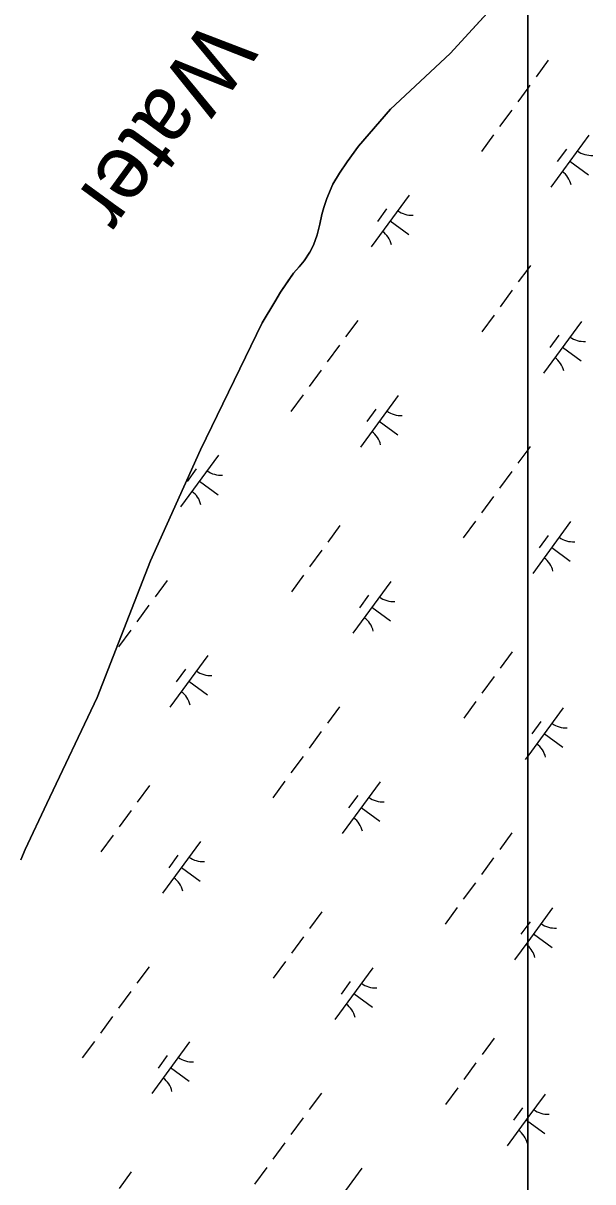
# Model space of a CAD drawing. Extents: x 3905714 to 3926767, y 183354 to 205755.
# Drawn here: x 3919109 to 3919552, y 191077 to 191979 of the extents above; entities that cross this region are included whole.
import ezdxf

# ---------------------------------------------------------------- set-up
doc = ezdxf.new("R2010")
doc.units = 0
for name, color, linetype in [('V-RIVR-IDEN', 7, 'Continuous'), ('V-TOPO-SHOR', 7, 'Continuous'), ('V-WETL-SWMP', 7, 'Continuous')]:
    doc.layers.add(name, color=color, linetype=linetype)

msp = doc.modelspace()

# ---------------------------------------------------------------- linework, layer by layer
at = {"layer": 'V-TOPO-SHOR'}
msp.add_lwpolyline([(3919106.72, 191327.57), (3919110.07, 191335.54), (3919126.95, 191371.52), (3919166.14, 191453.89), (3919207.77, 191560.46), (3919246.78, 191646.73), (3919294.71, 191745.65), (3919304.47, 191761.99), (3919309.04, 191769.54), (3919314.44, 191777.5), (3919319, 191784.24), (3919323.56, 191789.33), (3919327.28, 191794.02), (3919331.85, 191800.76), (3919334.55, 191806.07), (3919337.49, 191814.25), (3919339.6, 191822.44), (3919341.09, 191830.02), (3919342.78, 191835.55), (3919345.08, 191842.51), (3919349.68, 191853.55), (3919354.88, 191862.12), (3919360.89, 191871.11), (3919369.8, 191883.14), (3919394.64, 191911.88), (3919441.12, 191955.22), (3919496.14, 192015.52)], dxfattribs=at)
at = {"layer": 'V-WETL-SWMP'}
for p, q in [((3919501.47, 192024.2), (3919501.47, 190438.08)), ((3919501.47, 190438.08), (3919501.47, 192024.2)), ((3919496.14, 192015.52), (3919441.12, 191955.22)), ((3919441.12, 191955.22), (3919394.64, 191911.88)), ((3919517.35, 191950.03), (3919507.9, 191937.12)), ((3919501.47, 191928.34), (3919493.71, 191917.76)), ((3919503.17, 191930.67), (3919501.47, 191928.34)), ((3919394.64, 191911.88), (3919369.8, 191883.14)), ((3919488.99, 191911.31), (3919479.53, 191898.4)), ((3919474.8, 191891.95), (3919465.35, 191879.04)), ((3919548.99, 191891.62), (3919519.44, 191851.29)), ((3919369.8, 191883.14), (3919360.89, 191871.11)), ((3919531.53, 191880.86), (3919524.44, 191871.18)), ((3919360.89, 191871.11), (3919354.88, 191862.12)), ((3919534.21, 191871.46), (3919548.73, 191860.82)), ((3919354.88, 191862.12), (3919349.68, 191853.55)), ((3919349.68, 191853.55), (3919345.08, 191842.51)), ((3919409.03, 191845.11), (3919379.48, 191804.77)), ((3919345.08, 191842.51), (3919342.78, 191835.55)), ((3919341.09, 191830.02), (3919339.6, 191822.44)), ((3919342.78, 191835.55), (3919341.09, 191830.02)), ((3919391.58, 191834.34), (3919384.49, 191824.66)), ((3919339.6, 191822.44), (3919337.49, 191814.25)), ((3919394.26, 191824.94), (3919408.78, 191814.3)), ((3919337.49, 191814.25), (3919334.55, 191806.07)), ((3919331.85, 191800.76), (3919327.28, 191794.02)), ((3919334.55, 191806.07), (3919331.85, 191800.76)), ((3919327.28, 191794.02), (3919323.56, 191789.33)), ((3919319, 191784.24), (3919309.04, 191769.54)), ((3919323.56, 191789.33), (3919319, 191784.24)), ((3919501.47, 191787.48), (3919494.11, 191777.45)), ((3919503.57, 191790.35), (3919501.47, 191787.48)), ((3919309.04, 191769.54), (3919304.48, 191761.99)), ((3919489.39, 191770.99), (3919479.93, 191758.09)), ((3919304.48, 191761.99), (3919294.71, 191745.65)), ((3919369.04, 191747.59), (3919359.58, 191734.69)), ((3919475.2, 191751.63), (3919465.75, 191738.73)), ((3919543.21, 191746.8), (3919513.66, 191706.47)), ((3919294.71, 191745.65), (3919246.78, 191646.73)), ((3919354.86, 191728.23), (3919345.4, 191715.33)), ((3919525.76, 191736.03), (3919518.67, 191726.35)), ((3919528.44, 191726.63), (3919542.96, 191716)), ((3919340.67, 191708.87), (3919331.22, 191695.97)), ((3919326.49, 191689.51), (3919317.03, 191676.61)), ((3919400.67, 191689.19), (3919371.12, 191648.85)), ((3919383.22, 191678.42), (3919376.13, 191668.74)), ((3919385.9, 191669.02), (3919400.42, 191658.38)), ((3919246.78, 191646.73), (3919207.77, 191560.45)), ((3919501.47, 191646.9), (3919493.76, 191636.38)), ((3919503.22, 191649.29), (3919501.47, 191646.9)), ((3919260.72, 191642.67), (3919231.17, 191602.34)), ((3919243.26, 191631.9), (3919236.17, 191622.22)), ((3919489.04, 191629.93), (3919479.58, 191617.02)), ((3919245.94, 191622.5), (3919260.46, 191611.87)), ((3919474.85, 191610.57), (3919465.39, 191597.66)), ((3919355.26, 191587.92), (3919345.8, 191575.01)), ((3919460.67, 191591.21), (3919451.21, 191578.3)), ((3919534.85, 191590.88), (3919505.3, 191550.55)), ((3919517.4, 191580.11), (3919510.31, 191570.43)), ((3919341.07, 191568.56), (3919331.62, 191555.65)), ((3919520.08, 191570.71), (3919534.6, 191560.07)), ((3919207.77, 191560.45), (3919166.14, 191453.89)), ((3919326.89, 191549.2), (3919317.43, 191536.29)), ((3919220.73, 191545.16), (3919211.27, 191532.25)), ((3919394.9, 191544.36), (3919365.35, 191504.03)), ((3919377.44, 191533.6), (3919370.35, 191523.92)), ((3919206.54, 191525.8), (3919197.09, 191512.89)), ((3919380.12, 191524.2), (3919394.64, 191513.56)), ((3919192.36, 191506.44), (3919182.9, 191493.53)), ((3919252.36, 191486.75), (3919222.81, 191446.42)), ((3919489.43, 191489.61), (3919479.98, 191476.7)), ((3919234.9, 191475.98), (3919227.81, 191466.3)), ((3919237.58, 191466.58), (3919252.1, 191455.94)), ((3919475.25, 191470.25), (3919465.79, 191457.34)), ((3919166.14, 191453.89), (3919126.95, 191371.52)), ((3919461.07, 191450.89), (3919451.61, 191437.98)), ((3919354.9, 191446.85), (3919345.45, 191433.94)), ((3919529.08, 191446.06), (3919501.47, 191408.37)), ((3919511.62, 191435.29), (3919504.53, 191425.61)), ((3919340.72, 191427.49), (3919331.26, 191414.58)), ((3919514.3, 191425.89), (3919528.82, 191415.25)), ((3919326.54, 191408.13), (3919317.08, 191395.22)), ((3919501.47, 191408.37), (3919499.53, 191405.73)), ((3919206.94, 191385.48), (3919197.48, 191372.57)), ((3919312.35, 191388.77), (3919302.9, 191375.86)), ((3919386.54, 191388.44), (3919356.99, 191348.11)), ((3919369.08, 191377.68), (3919361.99, 191368)), ((3919126.95, 191371.52), (3919110.06, 191335.54)), ((3919371.76, 191368.28), (3919386.28, 191357.64)), ((3919192.76, 191366.12), (3919183.3, 191353.21)), ((3919178.57, 191346.76), (3919169.12, 191333.85)), ((3919246.58, 191341.93), (3919217.03, 191301.59)), ((3919489.08, 191348.55), (3919479.63, 191335.64)), ((3919110.06, 191335.54), (3919106.72, 191327.57)), ((3919229.13, 191331.16), (3919222.04, 191321.48)), ((3919474.9, 191329.19), (3919465.44, 191316.28)), ((3919231.81, 191321.76), (3919246.33, 191311.12)), ((3919460.72, 191309.82), (3919451.26, 191296.92)), ((3919341.12, 191287.17), (3919331.66, 191274.27)), ((3919446.53, 191290.46), (3919437.08, 191277.56)), ((3919520.72, 191290.14), (3919501.47, 191263.86)), ((3919501.47, 191276.92), (3919496.17, 191269.69)), ((3919503.26, 191279.37), (3919501.47, 191276.92)), ((3919326.94, 191267.81), (3919317.48, 191254.91)), ((3919505.94, 191269.97), (3919520.46, 191259.33)), ((3919501.47, 191263.86), (3919491.17, 191249.8)), ((3919206.59, 191244.41), (3919197.13, 191231.51)), ((3919312.75, 191248.45), (3919303.3, 191235.55)), ((3919380.76, 191243.62), (3919351.21, 191203.29)), ((3919363.31, 191232.85), (3919356.22, 191223.17)), ((3919192.41, 191225.05), (3919182.95, 191212.15)), ((3919365.99, 191223.45), (3919380.51, 191212.82)), ((3919178.22, 191205.69), (3919168.77, 191192.79)), ((3919475.3, 191188.87), (3919465.84, 191175.96)), ((3919164.04, 191186.33), (3919154.58, 191173.43)), ((3919238.22, 191186.01), (3919208.67, 191145.67)), ((3919220.77, 191175.24), (3919213.68, 191165.56)), ((3919461.12, 191169.51), (3919451.66, 191156.6)), ((3919223.45, 191165.84), (3919237.97, 191155.2)), ((3919340.77, 191146.11), (3919331.31, 191133.2)), ((3919446.93, 191150.15), (3919437.48, 191137.24)), ((3919514.94, 191145.32), (3919501.47, 191126.92)), ((3919497.49, 191134.55), (3919490.4, 191124.87)), ((3919326.59, 191126.75), (3919317.13, 191113.84)), ((3919501.47, 191126.92), (3919485.39, 191104.98)), ((3919500.17, 191125.15), (3919501.47, 191124.2)), ((3919501.47, 191124.2), (3919514.69, 191114.51)), ((3919312.4, 191107.39), (3919302.95, 191094.48)), ((3919298.22, 191088.03), (3919288.76, 191075.12)), ((3919372.4, 191087.7), (3919342.85, 191047.37)), ((3919192.81, 191084.74), (3919183.35, 191071.83))]:
    msp.add_line(p, q, dxfattribs=at)
for centre, start, end in [((3919550.73, 191893.6), 232.99998, 274.54364), ((3919518.08, 191849.03), 12.99998, 54.54364), ((3919410.77, 191847.08), 232.99998, 274.54364), ((3919378.12, 191802.52), 12.99998, 54.54364), ((3919544.95, 191748.78), 232.99998, 274.54364), ((3919512.3, 191704.21), 12.99998, 54.54364), ((3919402.41, 191691.16), 232.99998, 274.54364), ((3919369.76, 191646.6), 12.99998, 54.54364), ((3919262.46, 191644.64), 232.99998, 274.54364), ((3919229.81, 191600.08), 12.99998, 54.54364), ((3919536.59, 191592.85), 232.99998, 274.54364), ((3919503.94, 191548.29), 12.99998, 54.54364), ((3919396.64, 191546.34), 232.99998, 274.54364), ((3919363.99, 191501.78), 12.99998, 54.54364), ((3919254.1, 191488.72), 232.99998, 274.54364), ((3919221.45, 191444.16), 12.99998, 54.54364), ((3919530.82, 191448.03), 232.99998, 274.54364), ((3919498.17, 191403.47), 12.99998, 54.54364), ((3919388.28, 191390.42), 232.99998, 274.54364), ((3919355.63, 191345.85), 12.99998, 54.54364), ((3919248.32, 191343.9), 232.99998, 274.54364), ((3919215.67, 191299.34), 12.99998, 54.54364), ((3919522.46, 191292.11), 232.99998, 274.54364), ((3919489.81, 191247.55), 48.58181, 54.54364), ((3919489.81, 191247.55), 12.99998, 48.58181), ((3919382.5, 191245.6), 232.99998, 274.54364), ((3919349.85, 191201.03), 12.99998, 54.54364), ((3919239.96, 191187.98), 232.99998, 274.54364), ((3919207.31, 191143.42), 12.99998, 54.54364), ((3919516.68, 191147.29), 232.99998, 274.54364), ((3919484.03, 191102.73), 12.99998, 54.54364)]:
    msp.add_arc(centre, 17.62, start, end, dxfattribs=at)

# ---------------------------------------------------------------- texts
at = {"layer": 'V-RIVR-IDEN'}
msp.add_text('Water', height=50, rotation=233.87144, dxfattribs=at).set_placement((3919251.87, 191984.31))

doc.saveas('drawing.dxf')
